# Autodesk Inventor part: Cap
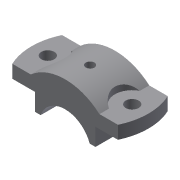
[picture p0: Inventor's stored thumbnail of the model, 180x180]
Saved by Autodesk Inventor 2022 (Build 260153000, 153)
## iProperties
Created: 2009-04
Part Number: Cap
Document SubType Name: Modeling
Designer: Sham
Density: 1 g/cm^3
Material: Generic
Appearance: Default
Mass: 94.0132 g
Surface Area: 184.419 cm^2
Volume: 94.0132 cm^3
Author: Sham
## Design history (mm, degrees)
sketch "Sketch1"
  geometry: L1 (-48.857, 23)-(48.857, 23); L2 (48.857, -23)-(-48.857, -23); A1 r 54 centre (0, 0) between (-48.857, 23) and (-48.857, -23); A2 r 54 centre (0, 0) between (48.857, -23) and (48.857, 23); 1 further point
  constraints: 4 end point, 4 point on circle, 2 centre point, 2 coincident, 1 horizontal, 1 parallel, 1 other
  dimensions: "d3" = 54 radius of A1; "d4" = 54 radius of A2; "d5" = 46 distance between parallel lines of L2 L1; "d6" = 23 distance from line of point (0, 0) L1
extrude "Extrusion1" new body sketch "Sketch1" distance "d7" = 12; taper "d8" = 0 deg
sketch "Sketch3"
  geometry: L1 (20.906, 0)-(20.906, -16); L2 (76.906, -0.137)-(76.906, -16.137); L3 (20.906, -16)-(26.23, -16); L4 (71.532, -16.137)-(76.906, -16.137); L5 (76.906, -0.137)-(76.857, 12); L6 (97.714, 0)-(0, 0) reference; L7 (76.857, 12)-(80.606, 12); L8 (17.108, 12)-(20.906, 12); L9 (20.906, 12)-(20.906, 0); L10 (0, 12)-(97.714, 12) reference; A1 r 24 centre (48.857, -24) between (71.532, -16.137) and (26.23, -16); A2 r 48 centre (48.857, -24) between (80.606, 12) and (17.108, 12); 3 further points
  constraints: 16 end point, 4 point on circle, 3 parallel, 3 perpendicular, 2 centre point, 2 coincident, 2 vertical alignment, 1 collinear, 1 midpoint, 1 vertical, 2 other
  dimensions: "d17" = 48 diameter of A1; "d18" = 16 distance of L1.start L1.end; "d19" = 56 distance between parallel lines of L2 L1; "d21" = 8 vertical distance of A1.centre L1.end; "d22" = 48 radius of A2; "d23" = 0 distance from line of L6 L1.start; "d38" = 31.74902 distance of L7.end point (48.857, 12); "d39" = 28 distance from line of point (48.857, 12) L5
extrude "Extrusion2" join sketch "Sketch3" stored distance "d24" = 12; taper "d25" = 0 deg
sketch "Sketch4"
  geometry: 2 further points
  dimensions: "d26" = 78 distance of point (39, 0) point (-39, 0)
hole "Hole1" sketch "Sketch4" at (-39, 0), (39, 0) diameter "d28" = 12; stored, may be unused: countersink angle "d32" = 90 deg, drill point angle "d34" = 118 deg; dims "d29" = 6, "d30" = 4, "d31" = 2, "d33" = 8
sketch "Sketch5"
  geometry: L1 (-31.749, -23)-(-31.749, 23) reference; L2 (-31.749, 14.263)-(-31.749, -14.263); C1 r 6 at (-39, 0) reference; A1 r 16 centre (-39, 0) between (-31.749, -14.263) and (-31.749, 14.263)
  constraints: 2 end point, 2 point on circle, 1 centre point, 1 coincident, 1 collinear, 1 point on line
  dimensions: "d35" = 16 radius of A1
extrude "Extrusion3" cut sketch "Sketch5" distance "d36" = 12; taper "d37" = 0 deg
mirror "Mirror2"
workplane "Work Plane4"
sketch "Sketch6"
  geometry: L1 (-31.749, 0)-(31.749, 0) reference; 1 further point
  dimensions: "d40" = 23 distance from line of L1 point (0, 23)
hole "Hole2" sketch "Sketch6" at (0, 23) diameter "d41" = 6; stored, may be unused: countersink angle "d45" = 90 deg, drill point angle "d47" = 118 deg; dims "d42" = 6, "d43" = 8, "d44" = 16, "d46" = 8
body "Solid1"
